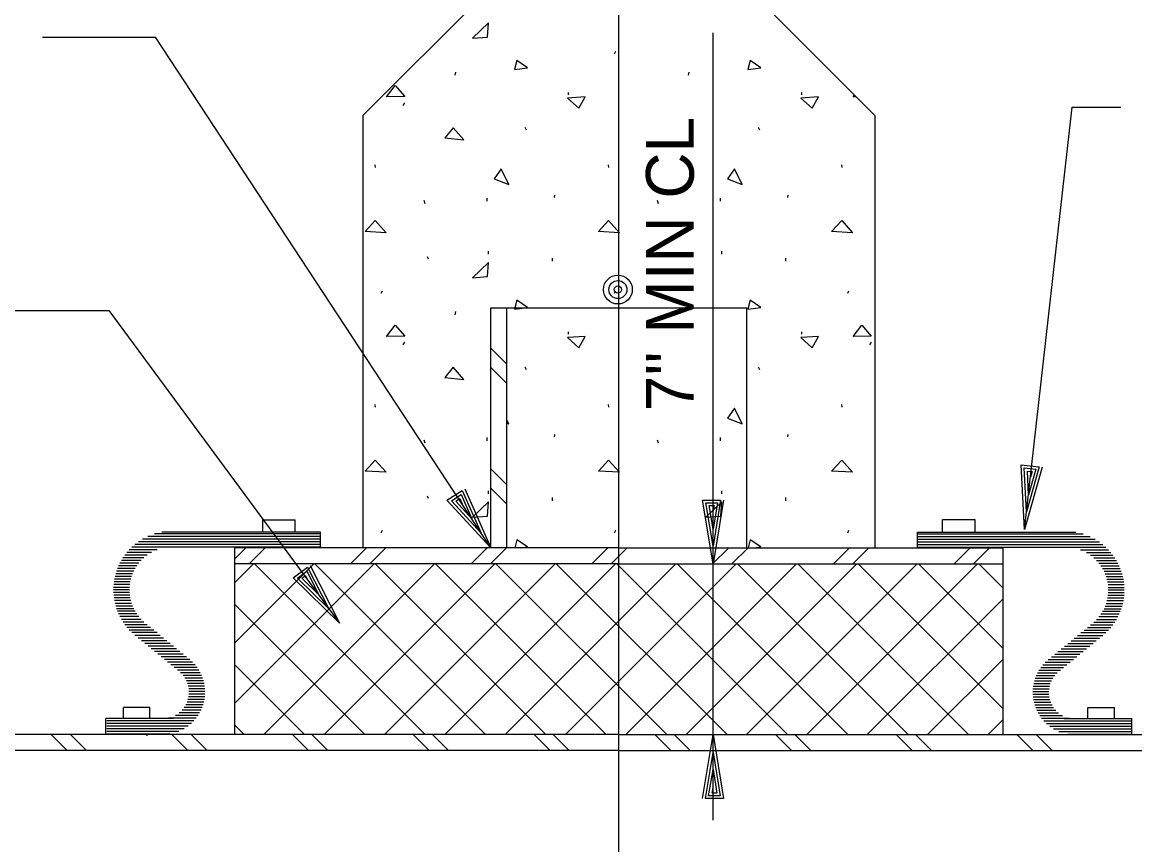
# Model space of a CAD drawing. Extents: x 22411.4 to 22495.4, y 22369.6 to 22415.
# Drawn here: x 22414.961 to 22419.306, y 22392.809 to 22396.021 of the extents above; entities that cross this region are included whole.
import ezdxf

# ---------------------------------------------------------------- set-up
doc = ezdxf.new("R2010")
doc.units = 0
for name, color, linetype in [('Level 1', 7, 'Continuous'), ('Level 2', 7, 'Continuous'), ('Level 4', 7, 'Continuous'), ('Level 7', 7, 'Continuous'), ('Level 8', 7, 'Continuous')]:
    doc.layers.add(name, color=color, linetype=linetype)

msp = doc.modelspace()

# ---------------------------------------------------------------- linework, layer by layer
at = {"layer": 'Level 1'}
for p, q in [((22417.2912, 22389.3264), (22417.2912, 22398.4141)), ((22417.6587, 22393.9058), (22417.6587, 22395.9792)), ((22417.274, 22394.9626), (22417.2786, 22394.9724)), ((22417.094, 22394.8026), (22417.0948, 22394.8118)), ((22418.0051, 22394.8026), (22418.0059, 22394.8118)), ((22417.8419, 22394.6635), (22417.8363, 22394.6745)), ((22418.1628, 22394.5182), (22418.1619, 22394.5285)), ((22416.7771, 22394.3866), (22416.7771, 22394.3991)), ((22416.5346, 22394.3766), (22416.5311, 22394.3891)), ((22416.7815, 22394.1793), (22416.7815, 22394.191)), ((22417.6926, 22394.1793), (22417.6926, 22394.191)), ((22418.8832, 22394.1091), (22418.8832, 22394.1091)), ((22415.9, 22394.0299), (22415.9, 22394.0776)), ((22415.9, 22394.0776), (22416.0274, 22394.0776)), ((22416.0274, 22394.0299), (22416.0274, 22394.0776)), ((22418.555, 22394.0299), (22418.555, 22394.0776)), ((22418.6824, 22394.0776), (22418.555, 22394.0776)), ((22418.6824, 22394.0299), (22418.6824, 22394.0776)), ((22416.7531, 22394.0262), (22416.7531, 22394.0262)), ((22418.8754, 22394.0402), (22418.8754, 22394.0402)), ((22416.7912, 22393.9683), (22416.7912, 22393.9683)), ((22417.6587, 22393.2391), (22417.6587, 22393.9058)), ((22416.1586, 22393.7307), (22416.1586, 22393.7307)), ((22416.1998, 22393.6749), (22416.1998, 22393.6749)), ((22415.3559, 22393.3014), (22415.3559, 22393.3444)), ((22415.4596, 22393.3444), (22415.3559, 22393.3444)), ((22415.4596, 22393.3014), (22415.4596, 22393.3444)), ((22419.1228, 22393.3014), (22419.1228, 22393.3444)), ((22419.1228, 22393.3444), (22419.2264, 22393.3444)), ((22419.2264, 22393.3014), (22419.2264, 22393.3444)), ((22417.6587, 22392.9045), (22417.6587, 22393.2391))]:
    msp.add_line(p, q, dxfattribs=at)
for points in [[(22416.3836, 22395.7291), (22416.4171, 22395.7735)], [(22418.2177, 22395.7294), (22418.2057, 22395.7291)], [(22416.8611, 22394.452), (22416.8537, 22394.4672)], [(22416.8537, 22394.4549), (22416.8611, 22394.452)], [(22417.7, 22394.1551), (22417.6587, 22393.9058), (22417.6174, 22394.1551), (22417.688, 22394.1551), (22417.6587, 22393.9751), (22417.6307, 22394.1445), (22417.676, 22394.1445), (22417.6587, 22394.0418), (22417.644, 22394.1338), (22417.6627, 22394.1338), (22417.6587, 22394.1111)], [(22417.8032, 22394.0003), (22417.7957, 22393.9683)], [(22416.9072, 22393.9683), (22416.9346, 22393.9718)], [(22417.8182, 22393.9683), (22417.8457, 22393.9718)], [(22417.6174, 22392.9898), (22417.6587, 22393.2391), (22417.7, 22392.9898), (22417.6294, 22392.9898), (22417.6587, 22393.1698), (22417.6867, 22393.0005), (22417.6414, 22393.0005), (22417.6587, 22393.1031), (22417.6734, 22393.0111), (22417.6547, 22393.0111), (22417.6587, 22393.0338)]]:
    msp.add_lwpolyline(points, dxfattribs=at)
at = {"layer": 'Level 2'}
for p, q in [((22415.04, 22395.962), (22415.482, 22395.962)), ((22416.7912, 22393.9683), (22415.482, 22395.962)), ((22418.8754, 22394.0402), (22419.0616, 22395.6893)), ((22419.0616, 22395.6893), (22419.2512, 22395.6893)), ((22413.3829, 22394.8951), (22415.2997, 22394.8951)), ((22415.2997, 22394.8951), (22416.1998, 22393.6749)), ((22416.7912, 22393.9683), (22416.7912, 22394.9059)), ((22416.7912, 22394.9059), (22417.7912, 22394.9059)), ((22416.8537, 22393.9683), (22416.8537, 22394.9059)), ((22417.7912, 22393.9683), (22417.7912, 22394.9059)), ((22416.1257, 22394.0299), (22415.5063, 22394.0299)), ((22416.1257, 22393.9683), (22416.1257, 22394.0299)), ((22418.4567, 22394.0299), (22419.0761, 22394.0299)), ((22418.4567, 22393.9683), (22418.4567, 22394.0299)), ((22417.2912, 22393.9683), (22415.7912, 22393.9683)), ((22415.7912, 22393.2391), (22415.7912, 22393.9683)), ((22417.2912, 22393.9683), (22418.7912, 22393.9683)), ((22418.7912, 22393.2391), (22418.7912, 22393.9683)), ((22417.2912, 22393.9058), (22415.7912, 22393.9058)), ((22417.2912, 22393.9058), (22418.7912, 22393.9058)), ((22415.5523, 22393.3014), (22415.2877, 22393.3014)), ((22415.2877, 22393.2391), (22415.2877, 22393.3014)), ((22419.0301, 22393.3014), (22419.2947, 22393.3014)), ((22419.2947, 22393.2391), (22419.2947, 22393.3014)), ((22417.2912, 22393.2391), (22412.0877, 22393.2391)), ((22415.4483, 22393.2347), (22415.4486, 22393.2388)), ((22417.2912, 22393.2391), (22422.4946, 22393.2391)), ((22417.2912, 22393.1766), (22412.1268, 22393.1766)), ((22417.2912, 22393.1766), (22422.4556, 22393.1766))]:
    msp.add_line(p, q, dxfattribs=at)
for points in [[(22418.9445, 22394.2833), (22418.8754, 22394.0402), (22418.8623, 22394.2926), (22418.9325, 22394.2846), (22418.8832, 22394.1091), (22418.8744, 22394.2805), (22418.9194, 22394.2754), (22418.8907, 22394.1753), (22418.8864, 22394.2684), (22418.905, 22394.2663), (22418.8985, 22394.2442)], [(22416.6889, 22394.1994), (22416.7912, 22393.9683), (22416.6198, 22394.154), (22416.6788, 22394.1928), (22416.7531, 22394.0262), (22416.6368, 22394.1524), (22416.6747, 22394.1773), (22416.7165, 22394.082), (22416.6538, 22394.1508), (22416.6694, 22394.1611), (22416.6785, 22394.1399)], [(22416.1245, 22394.0017), (22415.4309, 22394.0017)], [(22416.1245, 22394.0122), (22415.4509, 22394.0122)], [(22416.1245, 22394.0226), (22415.478, 22394.0226)], [(22418.4578, 22394.0226), (22419.1043, 22394.0226)], [(22418.4578, 22394.0122), (22419.1314, 22394.0122)], [(22418.4578, 22394.0017), (22419.1514, 22394.0017)], [(22415.4884, 22393.9601), (22415.3789, 22393.9601)], [(22416.1245, 22393.9705), (22415.3892, 22393.9705)], [(22416.1245, 22393.9809), (22415.401, 22393.9809)], [(22416.1245, 22393.9913), (22415.4147, 22393.9913)], [(22418.4578, 22393.9913), (22419.1677, 22393.9913)], [(22418.4578, 22393.9809), (22419.1813, 22393.9809)], [(22418.4578, 22393.9705), (22419.1932, 22393.9705)], [(22419.094, 22393.9601), (22419.2035, 22393.9601)], [(22415.4255, 22393.9184), (22415.3481, 22393.9184)], [(22415.4363, 22393.9288), (22415.3545, 22393.9288)], [(22415.4493, 22393.9392), (22415.3617, 22393.9392)], [(22415.4658, 22393.9497), (22415.3697, 22393.9497)], [(22419.1166, 22393.9497), (22419.2126, 22393.9497)], [(22419.1331, 22393.9392), (22419.2207, 22393.9392)], [(22419.1461, 22393.9288), (22419.2279, 22393.9288)], [(22419.1569, 22393.9184), (22419.2343, 22393.9184)], [(22415.3967, 22393.8767), (22415.3293, 22393.8767)], [(22415.4022, 22393.8872), (22415.3331, 22393.8872)], [(22415.4087, 22393.8976), (22415.3374, 22393.8976)], [(22415.4164, 22393.908), (22415.3424, 22393.908)], [(22416.085, 22393.9001), (22416.1998, 22393.6749), (22416.0185, 22393.851), (22416.0754, 22393.893), (22416.1586, 22393.7307), (22416.0356, 22393.8504), (22416.0721, 22393.8773), (22416.1191, 22393.7844), (22416.0526, 22393.8497), (22416.0677, 22393.8608), (22416.0779, 22393.8402)], [(22419.166, 22393.908), (22419.24, 22393.908)], [(22419.1736, 22393.8976), (22419.2449, 22393.8976)], [(22419.1802, 22393.8872), (22419.2493, 22393.8872)], [(22419.1857, 22393.8767), (22419.2531, 22393.8767)], [(22415.3829, 22393.8351), (22415.3195, 22393.8351)], [(22415.3852, 22393.8455), (22415.3212, 22393.8455)], [(22415.3882, 22393.8559), (22415.3234, 22393.8559)], [(22415.392, 22393.8663), (22415.3261, 22393.8663)], [(22419.1903, 22393.8663), (22419.2563, 22393.8663)], [(22419.1941, 22393.8559), (22419.259, 22393.8559)], [(22419.1972, 22393.8455), (22419.2611, 22393.8455)], [(22419.1995, 22393.8351), (22419.2628, 22393.8351)], [(22415.3799, 22393.8038), (22415.3174, 22393.8038)], [(22415.3802, 22393.8142), (22415.3177, 22393.8142)], [(22415.3803, 22393.7934), (22415.3177, 22393.7934)], [(22415.3812, 22393.8247), (22415.3184, 22393.8247)], [(22415.3812, 22393.783), (22415.3184, 22393.783)], [(22419.2011, 22393.783), (22419.264, 22393.783)], [(22419.2012, 22393.8247), (22419.264, 22393.8247)], [(22419.2021, 22393.8142), (22419.2647, 22393.8142)], [(22419.2021, 22393.7934), (22419.2647, 22393.7934)], [(22419.2024, 22393.8038), (22419.2649, 22393.8038)], [(22415.3829, 22393.7726), (22415.3196, 22393.7726)], [(22415.3852, 22393.7622), (22415.3213, 22393.7622)], [(22415.3883, 22393.7517), (22415.3234, 22393.7517)], [(22415.3921, 22393.7413), (22415.3261, 22393.7413)], [(22419.1902, 22393.7413), (22419.2562, 22393.7413)], [(22419.1941, 22393.7517), (22419.2589, 22393.7517)], [(22419.1971, 22393.7622), (22419.2611, 22393.7622)], [(22419.1995, 22393.7726), (22419.2628, 22393.7726)], [(22415.3968, 22393.7309), (22415.3294, 22393.7309)], [(22415.4023, 22393.7205), (22415.3331, 22393.7205)], [(22415.4088, 22393.7101), (22415.3375, 22393.7101)], [(22415.4166, 22393.6997), (22415.3425, 22393.6997)], [(22419.1658, 22393.6997), (22419.2399, 22393.6997)], [(22419.1735, 22393.7101), (22419.2448, 22393.7101)], [(22419.1801, 22393.7205), (22419.2492, 22393.7205)], [(22419.1856, 22393.7309), (22419.253, 22393.7309)], [(22415.4256, 22393.6892), (22415.3482, 22393.6892)], [(22415.4365, 22393.6788), (22415.3546, 22393.6788)], [(22415.449, 22393.6684), (22415.3618, 22393.6684)], [(22415.4618, 22393.658), (22415.3699, 22393.658)], [(22419.1206, 22393.658), (22419.2125, 22393.658)], [(22419.1333, 22393.6684), (22419.2206, 22393.6684)], [(22419.1459, 22393.6788), (22419.2278, 22393.6788)], [(22419.1567, 22393.6892), (22419.2342, 22393.6892)], [(22415.4746, 22393.6476), (22415.379, 22393.6476)], [(22415.4873, 22393.6372), (22415.3894, 22393.6372)], [(22415.5001, 22393.6267), (22415.4013, 22393.6267)], [(22415.5129, 22393.6163), (22415.414, 22393.6163)], [(22419.0695, 22393.6163), (22419.1684, 22393.6163)], [(22419.0823, 22393.6267), (22419.1811, 22393.6267)], [(22419.095, 22393.6372), (22419.193, 22393.6372)], [(22419.1078, 22393.6476), (22419.2033, 22393.6476)], [(22415.5256, 22393.6059), (22415.4268, 22393.6059)], [(22415.5384, 22393.5955), (22415.4395, 22393.5955)], [(22415.5512, 22393.5851), (22415.4523, 22393.5851)], [(22415.5639, 22393.5747), (22415.4651, 22393.5747)], [(22419.0184, 22393.5747), (22419.1173, 22393.5747)], [(22419.0312, 22393.5851), (22419.1301, 22393.5851)], [(22419.044, 22393.5955), (22419.1428, 22393.5955)], [(22419.0567, 22393.6059), (22419.1556, 22393.6059)], [(22415.5767, 22393.5642), (22415.4778, 22393.5642)], [(22415.5895, 22393.5538), (22415.4906, 22393.5538)], [(22415.6022, 22393.5434), (22415.5034, 22393.5434)], [(22415.615, 22393.533), (22415.5161, 22393.533)], [(22415.6263, 22393.5226), (22415.5289, 22393.5226)], [(22418.9561, 22393.5226), (22419.0535, 22393.5226)], [(22418.9674, 22393.533), (22419.0662, 22393.533)], [(22418.9801, 22393.5434), (22419.079, 22393.5434)], [(22418.9929, 22393.5538), (22419.0918, 22393.5538)], [(22419.0057, 22393.5642), (22419.1045, 22393.5642)], [(22415.6358, 22393.5122), (22415.5417, 22393.5122)], [(22415.6438, 22393.5017), (22415.5544, 22393.5017)], [(22415.6507, 22393.4913), (22415.5672, 22393.4913)], [(22415.6565, 22393.4809), (22415.5795, 22393.4809)], [(22418.9259, 22393.4809), (22419.0028, 22393.4809)], [(22418.9317, 22393.4913), (22419.0152, 22393.4913)], [(22418.9385, 22393.5017), (22419.0279, 22393.5017)], [(22418.9466, 22393.5122), (22419.0407, 22393.5122)], [(22415.6613, 22393.4705), (22415.5892, 22393.4705)], [(22415.6654, 22393.4601), (22415.5965, 22393.4601)], [(22415.6686, 22393.4497), (22415.6022, 22393.4497)], [(22415.6712, 22393.4392), (22415.6065, 22393.4392)], [(22418.9112, 22393.4392), (22418.9759, 22393.4392)], [(22418.9138, 22393.4497), (22418.9802, 22393.4497)], [(22418.917, 22393.4601), (22418.9858, 22393.4601)], [(22418.921, 22393.4705), (22418.9932, 22393.4705)], [(22415.673, 22393.4288), (22415.6095, 22393.4288)], [(22415.6741, 22393.4184), (22415.6113, 22393.4184)], [(22415.6745, 22393.3976), (22415.6119, 22393.3976)], [(22415.6747, 22393.408), (22415.6122, 22393.408)], [(22418.9077, 22393.408), (22418.9702, 22393.408)], [(22418.9079, 22393.3976), (22418.9704, 22393.3976)], [(22418.9082, 22393.4184), (22418.971, 22393.4184)], [(22418.9094, 22393.4288), (22418.9729, 22393.4288)], [(22415.6672, 22393.3559), (22415.5998, 22393.3559)], [(22415.6701, 22393.3663), (22415.6047, 22393.3663)], [(22415.6722, 22393.3767), (22415.6082, 22393.3767)], [(22415.6737, 22393.3872), (22415.6106, 22393.3872)], [(22418.9087, 22393.3872), (22418.9717, 22393.3872)], [(22418.9101, 22393.3767), (22418.9741, 22393.3767)], [(22418.9123, 22393.3663), (22418.9777, 22393.3663)], [(22418.9151, 22393.3559), (22418.9825, 22393.3559)], [(22415.6403, 22393.3038), (22415.5321, 22393.3038)], [(22415.6477, 22393.3142), (22415.5589, 22393.3142)], [(22415.6539, 22393.3247), (22415.5741, 22393.3247)], [(22415.6592, 22393.3351), (22415.5851, 22393.3351)], [(22415.6636, 22393.3455), (22415.5934, 22393.3455)], [(22418.9187, 22393.3455), (22418.9889, 22393.3455)], [(22418.9232, 22393.3351), (22418.9973, 22393.3351)], [(22418.9284, 22393.3247), (22419.0082, 22393.3247)], [(22418.9347, 22393.3142), (22419.0235, 22393.3142)], [(22418.942, 22393.3038), (22419.0502, 22393.3038)], [(22415.6316, 22393.2934), (22415.2912, 22393.2934)], [(22415.6214, 22393.283), (22415.2912, 22393.283)], [(22415.609, 22393.2726), (22415.2912, 22393.2726)], [(22415.5936, 22393.2622), (22415.2912, 22393.2622)], [(22418.9507, 22393.2934), (22419.2912, 22393.2934)], [(22418.961, 22393.283), (22419.2912, 22393.283)], [(22418.9734, 22393.2726), (22419.2912, 22393.2726)], [(22418.9887, 22393.2622), (22419.2912, 22393.2622)], [(22415.5731, 22393.2517), (22415.2912, 22393.2517)], [(22415.5385, 22393.2413), (22415.2912, 22393.2413)], [(22419.0092, 22393.2517), (22419.2912, 22393.2517)], [(22419.0438, 22393.2413), (22419.2912, 22393.2413)]]:
    msp.add_lwpolyline(points, dxfattribs=at)
for radius in [0.0563, 0.0352, 0.0141]:
    msp.add_circle((22417.2872, 22394.9769), radius, dxfattribs=at)
at = {"layer": 'Level 7'}
for p, q in [((22416.2912, 22395.6559), (22416.7912, 22396.1559)), ((22418.2912, 22395.6559), (22417.7912, 22396.1559)), ((22416.2912, 22395.6559), (22416.2912, 22393.9683)), ((22418.2912, 22395.6559), (22418.2912, 22393.9683))]:
    msp.add_line(p, q, dxfattribs=at)
at = {"layer": 'Level 8'}
for p, q in [((22417.274, 22395.8978), (22417.2786, 22395.9076)), ((22416.6521, 22395.8139), (22416.654, 22395.826)), ((22417.5632, 22395.8139), (22417.5651, 22395.826)), ((22417.094, 22395.7378), (22417.0948, 22395.747)), ((22418.0051, 22395.7378), (22418.0059, 22395.747)), ((22416.449, 22395.6962), (22416.4553, 22395.7066)), ((22416.9309, 22395.5987), (22416.9253, 22395.6097)), ((22417.8419, 22395.5987), (22417.8363, 22395.6097)), ((22416.3407, 22395.4535), (22416.3398, 22395.4637)), ((22417.2517, 22395.4535), (22417.2509, 22395.4637)), ((22418.1628, 22395.4535), (22418.1619, 22395.4637)), ((22417.0398, 22395.3366), (22417.0415, 22395.346)), ((22417.9509, 22395.3366), (22417.9526, 22395.346)), ((22416.5346, 22395.3118), (22416.5311, 22395.3243)), ((22416.7771, 22395.3218), (22416.7771, 22395.3343)), ((22417.4457, 22395.3118), (22417.4421, 22395.3243)), ((22417.6882, 22395.3218), (22417.6882, 22395.3343)), ((22416.5471, 22395.0962), (22416.5436, 22395.1051)), ((22416.7815, 22395.1145), (22416.7815, 22395.1262)), ((22417.0321, 22395.0876), (22417.0321, 22395.1001)), ((22417.6926, 22395.1145), (22417.6926, 22395.1262)), ((22417.9432, 22395.0876), (22417.9432, 22395.1001)), ((22416.363, 22394.9626), (22416.3676, 22394.9724)), ((22418.1851, 22394.9626), (22418.1896, 22394.9724)), ((22416.6521, 22394.8787), (22416.654, 22394.8907)), ((22416.449, 22394.761), (22416.4553, 22394.7714)), ((22418.2711, 22394.761), (22418.2773, 22394.7714)), ((22416.9309, 22394.6635), (22416.9253, 22394.6745)), ((22416.3407, 22394.5182), (22416.3398, 22394.5285)), ((22417.2517, 22394.5182), (22417.2509, 22394.5285)), ((22417.0398, 22394.4014), (22417.0415, 22394.4107)), ((22417.6882, 22394.3866), (22417.6882, 22394.3991)), ((22417.9509, 22394.4014), (22417.9526, 22394.4107)), ((22417.4457, 22394.3766), (22417.4421, 22394.3891)), ((22416.5471, 22394.161), (22416.5436, 22394.1699)), ((22417.0321, 22394.1524), (22417.0321, 22394.1649)), ((22417.9432, 22394.1524), (22417.9432, 22394.1649)), ((22416.363, 22394.0274), (22416.3676, 22394.0372)), ((22417.274, 22394.0274), (22417.2786, 22394.0372)), ((22418.1851, 22394.0274), (22418.1896, 22394.0372))]:
    msp.add_line(p, q, dxfattribs=at)
for points in [[(22416.7784, 22395.9628), (22416.7815, 22396.0185), (22416.7198, 22395.9582)], [(22416.884, 22395.8357), (22416.9346, 22395.8422), (22416.8921, 22395.8707)], [(22417.7951, 22395.8357), (22417.8457, 22395.8422), (22417.8032, 22395.8707)], [(22417.0909, 22395.7243), (22417.1353, 22395.6847), (22417.159, 22395.7291)], [(22418.0019, 22395.7243), (22418.0463, 22395.6847), (22418.0701, 22395.7291)], [(22416.6853, 22395.5612), (22416.644, 22395.6087), (22416.6109, 22395.5693)], [(22416.8042, 22395.4093), (22416.8611, 22395.3872), (22416.8311, 22395.4487)], [(22417.7153, 22395.4093), (22417.7721, 22395.3872), (22417.7421, 22395.4487)], [(22416.2998, 22395.2032), (22416.3394, 22395.2462), (22416.3819, 22395.1987)], [(22417.2109, 22395.2032), (22417.2505, 22395.2462), (22417.293, 22395.1987)], [(22418.1219, 22395.2032), (22418.1615, 22395.2462), (22418.204, 22395.1987)], [(22416.7784, 22395.0276), (22416.7815, 22395.0832), (22416.7198, 22395.023)], [(22416.884, 22394.9005), (22416.9346, 22394.907), (22416.8921, 22394.9355)], [(22417.7951, 22394.9005), (22417.8457, 22394.907), (22417.8032, 22394.9355)], [(22416.3836, 22394.7939), (22416.4171, 22394.8382), (22416.4548, 22394.7955)], [(22418.2057, 22394.7939), (22418.2392, 22394.8382), (22418.2769, 22394.7955)], [(22417.0909, 22394.7891), (22417.1353, 22394.7495), (22417.159, 22394.7939)], [(22418.0019, 22394.7891), (22418.0463, 22394.7495), (22418.0701, 22394.7939)], [(22416.6853, 22394.626), (22416.644, 22394.6735), (22416.6109, 22394.6341)], [(22417.7153, 22394.4741), (22417.7721, 22394.452), (22417.7421, 22394.5135)], [(22416.2998, 22394.268), (22416.3394, 22394.311), (22416.3819, 22394.2635)], [(22417.2109, 22394.268), (22417.2505, 22394.311), (22417.293, 22394.2635)], [(22418.1219, 22394.268), (22418.1615, 22394.311), (22418.204, 22394.2635)], [(22416.7784, 22394.0924), (22416.7815, 22394.148), (22416.7198, 22394.0878)], [(22417.6894, 22394.0924), (22417.6926, 22394.148), (22417.6309, 22394.0878)]]:
    msp.add_lwpolyline(points, close=True, dxfattribs=at)
for points in [[(22416.4171, 22395.7735), (22416.4548, 22395.7307)], [(22416.4548, 22395.7307), (22416.3836, 22395.7291)], [(22418.2057, 22395.7291), (22418.211, 22395.7361)], [(22416.8537, 22394.6862), (22416.7912, 22394.7487)], [(22416.8537, 22394.6107), (22416.7912, 22394.6732)], [(22416.8537, 22394.2148), (22416.7912, 22394.2773)], [(22416.8537, 22394.1393), (22416.7912, 22394.2018)], [(22416.8921, 22394.0003), (22416.8847, 22393.9683)], [(22416.9346, 22393.9718), (22416.8921, 22394.0003)], [(22417.8457, 22393.9718), (22417.8032, 22394.0003)], [(22415.7912, 22393.9252), (22415.8342, 22393.9683)], [(22415.8471, 22393.9058), (22415.9097, 22393.9683)], [(22416.2431, 22393.9058), (22416.3056, 22393.9683)], [(22416.3185, 22393.9058), (22416.3811, 22393.9683)], [(22416.7145, 22393.9058), (22416.777, 22393.9683)], [(22416.79, 22393.9058), (22416.8525, 22393.9683)], [(22417.1859, 22393.9058), (22417.2484, 22393.9683)], [(22417.2614, 22393.9058), (22417.3239, 22393.9683)], [(22417.6573, 22393.9058), (22417.7198, 22393.9683)], [(22417.7328, 22393.9058), (22417.7953, 22393.9683)], [(22418.1287, 22393.9058), (22418.1912, 22393.9683)], [(22418.2042, 22393.9058), (22418.2667, 22393.9683)], [(22418.6002, 22393.9058), (22418.6626, 22393.9683)], [(22418.6756, 22393.9058), (22418.7381, 22393.9683)], [(22415.7912, 22393.3619), (22416.3351, 22393.9058)], [(22415.7912, 22393.5976), (22416.0994, 22393.9058)], [(22415.7912, 22393.8333), (22415.8637, 22393.9058)], [(22416.5349, 22393.2391), (22415.8682, 22393.9058)], [(22415.9041, 22393.2391), (22416.5708, 22393.9058)], [(22416.7706, 22393.2391), (22416.1039, 22393.9058)], [(22416.1398, 22393.2391), (22416.8065, 22393.9058)], [(22417.0063, 22393.2391), (22416.3396, 22393.9058)], [(22416.3755, 22393.2391), (22417.0422, 22393.9058)], [(22417.242, 22393.2391), (22416.5753, 22393.9058)], [(22416.6112, 22393.2391), (22417.2779, 22393.9058)], [(22417.4777, 22393.2391), (22416.811, 22393.9058)], [(22416.8469, 22393.2391), (22417.5136, 22393.9058)], [(22417.7134, 22393.2391), (22417.0467, 22393.9058)], [(22417.0826, 22393.2391), (22417.7493, 22393.9058)], [(22417.9491, 22393.2391), (22417.2824, 22393.9058)], [(22417.3183, 22393.2391), (22417.985, 22393.9058)], [(22418.1848, 22393.2391), (22417.5181, 22393.9058)], [(22417.554, 22393.2391), (22418.2207, 22393.9058)], [(22418.4205, 22393.2391), (22417.7538, 22393.9058)], [(22417.7897, 22393.2391), (22418.4564, 22393.9058)], [(22418.6562, 22393.2391), (22417.9895, 22393.9058)], [(22418.0254, 22393.2391), (22418.6921, 22393.9058)], [(22418.7912, 22393.3398), (22418.2252, 22393.9058)], [(22418.7912, 22393.5755), (22418.4609, 22393.9058)], [(22418.7912, 22393.8112), (22418.6966, 22393.9058)], [(22416.2992, 22393.2391), (22415.7912, 22393.7471)], [(22418.2612, 22393.2391), (22418.7912, 22393.7692)], [(22418.4968, 22393.2391), (22418.7912, 22393.5335)], [(22416.0635, 22393.2391), (22415.7912, 22393.5114)], [(22415.8278, 22393.2391), (22415.7912, 22393.2757)], [(22418.7326, 22393.2391), (22418.7912, 22393.2977)], [(22415.1365, 22393.1766), (22415.074, 22393.2391)], [(22415.2119, 22393.1766), (22415.1494, 22393.2391)], [(22415.6079, 22393.1766), (22415.5454, 22393.2391)], [(22415.6833, 22393.1766), (22415.6208, 22393.2391)], [(22416.0793, 22393.1766), (22416.0168, 22393.2391)], [(22416.1547, 22393.1766), (22416.0922, 22393.2391)], [(22416.5507, 22393.1766), (22416.4882, 22393.2391)], [(22416.6261, 22393.1766), (22416.5636, 22393.2391)], [(22417.0221, 22393.1766), (22416.9596, 22393.2391)], [(22417.0975, 22393.1766), (22417.035, 22393.2391)], [(22417.4935, 22393.1766), (22417.431, 22393.2391)], [(22417.5689, 22393.1766), (22417.5064, 22393.2391)], [(22417.9649, 22393.1766), (22417.9024, 22393.2391)], [(22418.0403, 22393.1766), (22417.9778, 22393.2391)], [(22418.4363, 22393.1766), (22418.3738, 22393.2391)], [(22418.5117, 22393.1766), (22418.4492, 22393.2391)], [(22418.9077, 22393.1766), (22418.8452, 22393.2391)], [(22418.9831, 22393.1766), (22418.9207, 22393.2391)]]:
    msp.add_lwpolyline(points, dxfattribs=at)

# ---------------------------------------------------------------- texts
at = {"layer": 'Level 4'}
msp.add_text("7'' MIN CL", height=0.18667, rotation=90, dxfattribs=at).set_placement((22417.5836, 22394.5016))

doc.saveas('drawing.dxf')
